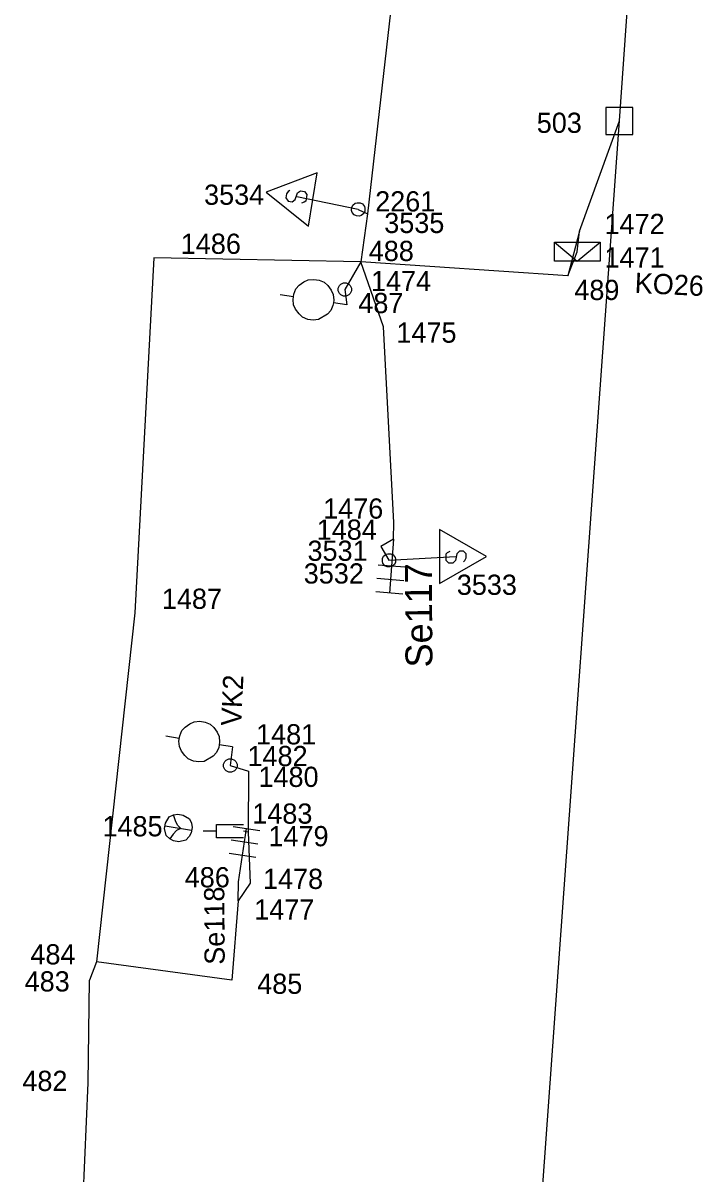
# Model space of a CAD drawing. Extents: x -535557 to -534097, y -1142175 to -1136716.
# Drawn here: x -534487.51 to -534462.19, y -1141424.56 to -1141381.9 of the extents above; entities that cross this region are included whole.
import ezdxf

# ---------------------------------------------------------------- set-up
doc = ezdxf.new("R2010")
doc.units = 0
doc.layers.add('Default', color=7, linetype='Continuous')
doc.layers.add('SS_SZDC', color=7, linetype='Continuous')

# ---------------------------------------------------------------- blocks, each defined once
blk = doc.blocks.new('POINT_DISPLAY')
at = {"layer": 'Default'}
blk.add_line((0, 0), (0, 0), dxfattribs=at)

msp = doc.modelspace()

# ---------------------------------------------------------------- linework, layer by layer
at = {"layer": 'SS_SZDC'}
for p, q in [((-534465.369, -1141385.53), (-534462.189, -1141340.389)), ((-534473.779, -1141380.75), (-534474.719, -1141388.97)), ((-534464.873, -1141385.026), (-534465.873, -1141385.033)), ((-534465.873, -1141385.033), (-534465.866, -1141386.033)), ((-534464.866, -1141386.026), (-534464.873, -1141385.026)), ((-534468.59, -1141430.27), (-534465.369, -1141385.53)), ((-534466.85, -1141389.62), (-534465.369, -1141385.53)), ((-534465.866, -1141386.033), (-534464.866, -1141386.026)), ((-534476.59, -1141387.456), (-534478.475, -1141388.17)), ((-534476.903, -1141389.431), (-534476.59, -1141387.456)), ((-534478.475, -1141388.17), (-534476.903, -1141389.431)), ((-534477.727, -1141388.238), (-534477.75, -1141388.386)), ((-534477.662, -1141388.147), (-534477.727, -1141388.238)), ((-534477.605, -1141388.105), (-534477.662, -1141388.147)), ((-534477.405, -1141388.44), (-534477.316, -1141388.201)), ((-534477.316, -1141388.201), (-534477.202, -1141388.118)), ((-534477.202, -1141388.118), (-534477.053, -1141388.142)), ((-534477.053, -1141388.142), (-534476.97, -1141388.256)), ((-534477.75, -1141388.386), (-534477.667, -1141388.5)), ((-534477.667, -1141388.5), (-534477.519, -1141388.524)), ((-534477.519, -1141388.524), (-534477.405, -1141388.44)), ((-534475.06, -1141388.809), (-534477.34, -1141388.35)), ((-534477.067, -1141388.545), (-534477.173, -1141388.578)), ((-534477.009, -1141388.503), (-534477.067, -1141388.545)), ((-534476.97, -1141388.256), (-534477.009, -1141388.503)), ((-534475.305, -1141388.741), (-534475.26, -1141388.651)), ((-534475.26, -1141388.651), (-534475.17, -1141388.585)), ((-534475.17, -1141388.585), (-534475.102, -1141388.563)), ((-534475.102, -1141388.563), (-534474.991, -1141388.564)), ((-534474.991, -1141388.564), (-534474.901, -1141388.609)), ((-534474.901, -1141388.609), (-534474.835, -1141388.699)), ((-534475.306, -1141388.852), (-534475.305, -1141388.741)), ((-534475.284, -1141388.92), (-534475.306, -1141388.852)), ((-534475.218, -1141389.01), (-534475.284, -1141388.92)), ((-534475.128, -1141389.055), (-534475.218, -1141389.01)), ((-534475.017, -1141389.056), (-534475.128, -1141389.055)), ((-534475.06, -1141388.809), (-534474.719, -1141388.97)), ((-534474.949, -1141389.034), (-534475.017, -1141389.056)), ((-534474.719, -1141388.97), (-534474.97, -1141390.76)), ((-534474.859, -1141388.968), (-534474.949, -1141389.034)), ((-534474.814, -1141388.878), (-534474.859, -1141388.968)), ((-534474.835, -1141388.699), (-534474.813, -1141388.767)), ((-534474.813, -1141388.767), (-534474.814, -1141388.878)), ((-534466.85, -1141389.62), (-534467.279, -1141391.28)), ((-534466.93, -1141390.379), (-534466.85, -1141389.62)), ((-534467.78, -1141390.029), (-534466.08, -1141390.029)), ((-534467.78, -1141390.729), (-534467.78, -1141390.029)), ((-534467.78, -1141390.029), (-534466.93, -1141390.729)), ((-534467.279, -1141391.28), (-534466.93, -1141390.379)), ((-534466.93, -1141390.729), (-534466.08, -1141390.029)), ((-534466.08, -1141390.029), (-534466.08, -1141390.729)), ((-534482.649, -1141390.61), (-534483.35, -1141403.78)), ((-534474.97, -1141390.76), (-534482.649, -1141390.61)), ((-534474.97, -1141390.76), (-534475.56, -1141391.78)), ((-534467.279, -1141391.28), (-534474.97, -1141390.76)), ((-534474.119, -1141393.17), (-534474.97, -1141390.76)), ((-534466.08, -1141390.729), (-534467.78, -1141390.729)), ((-534477.372, -1141391.76), (-534477.251, -1141391.627)), ((-534477.251, -1141391.627), (-534477.08, -1141391.501)), ((-534477.08, -1141391.501), (-534476.917, -1141391.425)), ((-534476.917, -1141391.425), (-534476.712, -1141391.406)), ((-534476.712, -1141391.406), (-534476.514, -1141391.436)), ((-534476.514, -1141391.436), (-534476.324, -1141391.515)), ((-534476.324, -1141391.515), (-534476.19, -1141391.636)), ((-534476.19, -1141391.636), (-534476.065, -1141391.807)), ((-534475.81, -1141391.73), (-534475.76, -1141391.63)), ((-534475.76, -1141391.63), (-534475.71, -1141391.58)), ((-534475.71, -1141391.58), (-534475.61, -1141391.53)), ((-534475.61, -1141391.53), (-534475.51, -1141391.53)), ((-534475.51, -1141391.53), (-534475.41, -1141391.58)), ((-534475.41, -1141391.58), (-534475.36, -1141391.63)), ((-534475.36, -1141391.63), (-534475.31, -1141391.73)), ((-534477.467, -1141392.05), (-534477.961, -1141391.975)), ((-534477.482, -1141392.148), (-534477.452, -1141391.951)), ((-534477.452, -1141391.951), (-534477.372, -1141391.76)), ((-534476.065, -1141391.807), (-534475.988, -1141391.97)), ((-534475.988, -1141391.97), (-534475.969, -1141392.176)), ((-534475.81, -1141391.83), (-534475.81, -1141391.73)), ((-534475.76, -1141391.93), (-534475.81, -1141391.83)), ((-534475.71, -1141391.98), (-534475.76, -1141391.93)), ((-534475.61, -1141392.03), (-534475.71, -1141391.98)), ((-534475.51, -1141392.03), (-534475.61, -1141392.03)), ((-534475.56, -1141391.78), (-534475.489, -1141392.35)), ((-534475.41, -1141391.98), (-534475.51, -1141392.03)), ((-534475.36, -1141391.93), (-534475.41, -1141391.98)), ((-534475.31, -1141391.83), (-534475.36, -1141391.93)), ((-534475.31, -1141391.73), (-534475.31, -1141391.83)), ((-534477.462, -1141392.354), (-534477.482, -1141392.148)), ((-534477.386, -1141392.517), (-534477.462, -1141392.354)), ((-534477.26, -1141392.688), (-534477.386, -1141392.517)), ((-534475.999, -1141392.373), (-534476.078, -1141392.564)), ((-534475.984, -1141392.275), (-534475.999, -1141392.373)), ((-534475.969, -1141392.176), (-534475.984, -1141392.275)), ((-534475.489, -1141392.35), (-534475.984, -1141392.275)), ((-534477.127, -1141392.809), (-534477.26, -1141392.688)), ((-534476.937, -1141392.889), (-534477.127, -1141392.809)), ((-534476.739, -1141392.919), (-534476.937, -1141392.889)), ((-534476.534, -1141392.899), (-534476.739, -1141392.919)), ((-534476.2, -1141392.697), (-534476.534, -1141392.899)), ((-534476.078, -1141392.564), (-534476.2, -1141392.697)), ((-534473.739, -1141400.42), (-534474.119, -1141393.17)), ((-534473.75, -1141401.049), (-534473.739, -1141400.42)), ((-534473.75, -1141401.049), (-534474.22, -1141401.319)), ((-534473.75, -1141401.049), (-534473.906, -1141403.043)), ((-534472.049, -1141400.69), (-534472.049, -1141402.69)), ((-534470.299, -1141401.69), (-534472.049, -1141400.69)), ((-534474.22, -1141401.319), (-534473.92, -1141401.829)), ((-534474.166, -1141401.872), (-534474.165, -1141401.761)), ((-534474.144, -1141401.94), (-534474.166, -1141401.872)), ((-534474.165, -1141401.761), (-534474.12, -1141401.671)), ((-534474.12, -1141401.671), (-534474.03, -1141401.605)), ((-534474.03, -1141401.605), (-534473.962, -1141401.583)), ((-534473.962, -1141401.583), (-534473.851, -1141401.584)), ((-534473.92, -1141401.829), (-534471.449, -1141401.69)), ((-534473.851, -1141401.584), (-534473.761, -1141401.629)), ((-534473.761, -1141401.629), (-534473.695, -1141401.719)), ((-534473.674, -1141401.898), (-534473.719, -1141401.988)), ((-534473.695, -1141401.719), (-534473.673, -1141401.787)), ((-534473.673, -1141401.787), (-534473.674, -1141401.898)), ((-534472.049, -1141402.69), (-534470.299, -1141401.69)), ((-534471.799, -1141401.59), (-534471.749, -1141401.54)), ((-534471.799, -1141401.84), (-534471.799, -1141401.59)), ((-534471.699, -1141401.94), (-534471.799, -1141401.84)), ((-534471.749, -1141401.54), (-534471.649, -1141401.49)), ((-534471.449, -1141401.84), (-534471.549, -1141401.94)), ((-534471.399, -1141401.59), (-534471.449, -1141401.84)), ((-534471.299, -1141401.49), (-534471.399, -1141401.59)), ((-534471.149, -1141401.49), (-534471.299, -1141401.49)), ((-534471.049, -1141401.59), (-534471.149, -1141401.49)), ((-534471.149, -1141401.89), (-534471.099, -1141401.84)), ((-534471.099, -1141401.84), (-534471.049, -1141401.74)), ((-534471.049, -1141401.74), (-534471.049, -1141401.59)), ((-534473.33, -1141402.086), (-534474.326, -1141402.007)), ((-534474.078, -1141402.03), (-534474.144, -1141401.94)), ((-534473.988, -1141402.075), (-534474.078, -1141402.03)), ((-534473.877, -1141402.076), (-534473.988, -1141402.075)), ((-534473.809, -1141402.054), (-534473.877, -1141402.076)), ((-534473.719, -1141401.988), (-534473.809, -1141402.054)), ((-534471.549, -1141401.94), (-534471.699, -1141401.94)), ((-534473.369, -1141402.584), (-534474.366, -1141402.506)), ((-534473.408, -1141403.083), (-534474.405, -1141403.004)), ((-534483.35, -1141403.78), (-534484.779, -1141416.729)), ((-534481.315, -1141407.891), (-534481.151, -1141407.816)), ((-534481.151, -1141407.816), (-534480.946, -1141407.798)), ((-534480.946, -1141407.798), (-534480.748, -1141407.829)), ((-534480.748, -1141407.829), (-534480.558, -1141407.91)), ((-534481.689, -1141408.338), (-534481.609, -1141408.148)), ((-534481.609, -1141408.148), (-534481.486, -1141408.016)), ((-534481.486, -1141408.016), (-534481.315, -1141407.891)), ((-534480.558, -1141407.91), (-534480.426, -1141408.032)), ((-534480.426, -1141408.032), (-534480.301, -1141408.203)), ((-534480.301, -1141408.203), (-534480.226, -1141408.367)), ((-534481.705, -1141408.437), (-534482.199, -1141408.358)), ((-534481.721, -1141408.535), (-534481.689, -1141408.338)), ((-534481.702, -1141408.741), (-534481.721, -1141408.535)), ((-534480.223, -1141408.671), (-534480.239, -1141408.77)), ((-534480.226, -1141408.367), (-534480.208, -1141408.573)), ((-534480.208, -1141408.573), (-534480.223, -1141408.671)), ((-534479.729, -1141408.75), (-534480.223, -1141408.671)), ((-534481.627, -1141408.905), (-534481.702, -1141408.741)), ((-534481.502, -1141409.076), (-534481.627, -1141408.905)), ((-534481.37, -1141409.198), (-534481.502, -1141409.076)), ((-534480.442, -1141409.092), (-534480.777, -1141409.292)), ((-534480.32, -1141408.96), (-534480.442, -1141409.092)), ((-534480.239, -1141408.77), (-534480.32, -1141408.96)), ((-534479.729, -1141408.75), (-534479.81, -1141409.44)), ((-534481.18, -1141409.279), (-534481.37, -1141409.198)), ((-534480.983, -1141409.31), (-534481.18, -1141409.279)), ((-534480.777, -1141409.292), (-534480.983, -1141409.31)), ((-534480.06, -1141409.39), (-534480.01, -1141409.29)), ((-534480.06, -1141409.49), (-534480.06, -1141409.39)), ((-534480.01, -1141409.59), (-534480.06, -1141409.49)), ((-534480.01, -1141409.29), (-534479.96, -1141409.24)), ((-534479.96, -1141409.24), (-534479.86, -1141409.19)), ((-534479.86, -1141409.19), (-534479.76, -1141409.19)), ((-534479.81, -1141409.44), (-534479.13, -1141409.649)), ((-534479.76, -1141409.19), (-534479.66, -1141409.24)), ((-534479.66, -1141409.24), (-534479.61, -1141409.29)), ((-534479.61, -1141409.29), (-534479.56, -1141409.39)), ((-534479.56, -1141409.49), (-534479.61, -1141409.59)), ((-534479.56, -1141409.39), (-534479.56, -1141409.49)), ((-534479.96, -1141409.64), (-534480.01, -1141409.59)), ((-534479.86, -1141409.69), (-534479.96, -1141409.64)), ((-534479.76, -1141409.69), (-534479.86, -1141409.69)), ((-534479.66, -1141409.64), (-534479.76, -1141409.69)), ((-534479.61, -1141409.59), (-534479.66, -1141409.64)), ((-534479.13, -1141409.649), (-534479.149, -1141411.909)), ((-534482.08, -1141411.351), (-534481.916, -1141411.276)), ((-534481.916, -1141411.276), (-534481.76, -1141411.25)), ((-534481.849, -1141411.489), (-534481.916, -1141411.276)), ((-534481.76, -1141411.25), (-534481.563, -1141411.281)), ((-534481.563, -1141411.281), (-534481.331, -1141411.419)), ((-534482.249, -1141411.78), (-534482.218, -1141411.583)), ((-534482.233, -1141411.681), (-534481.246, -1141411.838)), ((-534482.218, -1141411.583), (-534482.08, -1141411.351)), ((-534481.773, -1141411.653), (-534481.849, -1141411.489)), ((-534481.641, -1141411.775), (-534481.773, -1141411.653)), ((-534481.331, -1141411.419), (-534481.256, -1141411.583)), ((-534481.256, -1141411.583), (-534481.23, -1141411.739)), ((-534480.319, -1141412.129), (-534480.319, -1141411.629)), ((-534480.319, -1141411.629), (-534479.319, -1141411.629)), ((-534479.704, -1141411.707), (-534478.715, -1141411.857)), ((-534482.189, -1141412.043), (-534482.249, -1141411.78)), ((-534482.057, -1141412.165), (-534482.189, -1141412.043)), ((-534481.927, -1141411.983), (-534482.057, -1141412.165)), ((-534481.805, -1141411.85), (-534481.927, -1141411.983)), ((-534481.641, -1141411.775), (-534481.805, -1141411.85)), ((-534481.334, -1141412.077), (-534481.456, -1141412.209)), ((-534481.261, -1141411.936), (-534481.334, -1141412.077)), ((-534481.23, -1141411.739), (-534481.261, -1141411.936)), ((-534480.319, -1141411.879), (-534480.819, -1141411.879)), ((-534479.319, -1141412.129), (-534480.319, -1141412.129)), ((-534479.51, -1141413.76), (-534479.21, -1141411.782)), ((-534479.149, -1141411.909), (-534479.319, -1141411.879)), ((-534479.149, -1141411.909), (-534479.079, -1141413.809)), ((-534481.916, -1141412.238), (-534482.057, -1141412.165)), ((-534481.719, -1141412.269), (-534481.916, -1141412.238)), ((-534481.456, -1141412.209), (-534481.719, -1141412.269)), ((-534479.779, -1141412.201), (-534478.79, -1141412.351)), ((-534479.854, -1141412.696), (-534478.865, -1141412.846)), ((-534479.52, -1141414.459), (-534479.51, -1141413.76)), ((-534479.079, -1141413.809), (-534479.52, -1141414.459)), ((-534479.52, -1141414.459), (-534479.75, -1141417.409)), ((-534484.779, -1141416.729), (-534485.039, -1141417.399)), ((-534479.75, -1141417.409), (-534484.779, -1141416.729)), ((-534485.09, -1141421.219), (-534485.039, -1141417.399)), ((-534486.069, -1141443.729), (-534485.09, -1141421.219))]:
    msp.add_line(p, q, dxfattribs=at)

# ---------------------------------------------------------------- block references
for p in [(-534465.369, -1141385.53), (-534477.34, -1141388.35), (-534475.06, -1141388.809), (-534475.06, -1141388.809), (-534474.719, -1141388.97), (-534466.85, -1141389.62), (-534466.93, -1141390.379), (-534482.649, -1141390.61), (-534474.97, -1141390.76), (-534467.279, -1141391.28), (-534475.56, -1141391.78), (-534475.56, -1141391.78), (-534475.489, -1141392.35), (-534474.119, -1141393.17), (-534473.739, -1141400.42), (-534473.75, -1141401.049), (-534474.22, -1141401.319), (-534473.92, -1141401.829), (-534473.92, -1141401.829), (-534471.449, -1141401.69), (-534483.35, -1141403.78), (-534479.729, -1141408.75), (-534479.81, -1141409.44), (-534479.81, -1141409.44), (-534479.13, -1141409.649), (-534481.739, -1141411.76), (-534479.319, -1141411.879), (-534479.149, -1141411.909), (-534479.51, -1141413.76), (-534479.079, -1141413.809), (-534479.52, -1141414.459), (-534484.779, -1141416.729), (-534485.039, -1141417.399), (-534479.75, -1141417.409), (-534485.09, -1141421.219)]:
    msp.add_blockref('POINT_DISPLAY', p, dxfattribs=at)

# ---------------------------------------------------------------- texts
for s, p in [('503', (-534468.435, -1141385.971)), ('3534', (-534480.784, -1141388.64)), ('2261', (-534474.433, -1141388.887)), ('3535', (-534474.096, -1141389.687)), ('1472', (-534465.92, -1141389.725)), ('1486', (-534481.649, -1141390.46)), ('488', (-534474.671, -1141390.726)), ('1471', (-534465.92, -1141390.97)), ('1474', (-534474.587, -1141391.843)), ('489', (-534467.039, -1141392.173)), ('487', (-534475.058, -1141392.659)), ('1475', (-534473.644, -1141393.756)), ('1476', (-534476.364, -1141400.282)), ('1484', (-534476.604, -1141401.065)), ('3531', (-534476.945, -1141401.848)), ('3532', (-534477.084, -1141402.691)), ('3533', (-534471.403, -1141403.11)), ('1487', (-534482.35, -1141403.63)), ('1481', (-534478.853, -1141408.658)), ('1482', (-534479.172, -1141409.465)), ('1480', (-534478.765, -1141410.236)), ('1483', (-534478.994, -1141411.6)), ('1485', (-534484.555, -1141412.07)), ('1479', (-534478.394, -1141412.437)), ('486', (-534481.502, -1141413.962)), ('1478', (-534478.597, -1141414.021)), ('1477', (-534478.923, -1141415.158)), ('484', (-534487.23, -1141416.821)), ('483', (-534487.444, -1141417.824)), ('485', (-534478.811, -1141417.912)), ('482', (-534487.529, -1141421.516))]:
    msp.add_text(s, height=0.75, dxfattribs=at).set_placement(p)
for s, height, rotation, p in [('KO26', 0.75, 357.3, (-534464.812, -1141391.906)), ('Se117', 1, 90.3756, (-534472.305, -1141405.802)), ('VK2', 0.75, 87.3, (-534479.409, -1141407.987)), ('Se118', 0.75, 90.3756, (-534480.016, -1141416.831))]:
    msp.add_text(s, height=height, rotation=rotation, dxfattribs=at).set_placement(p)

doc.saveas('drawing.dxf')
